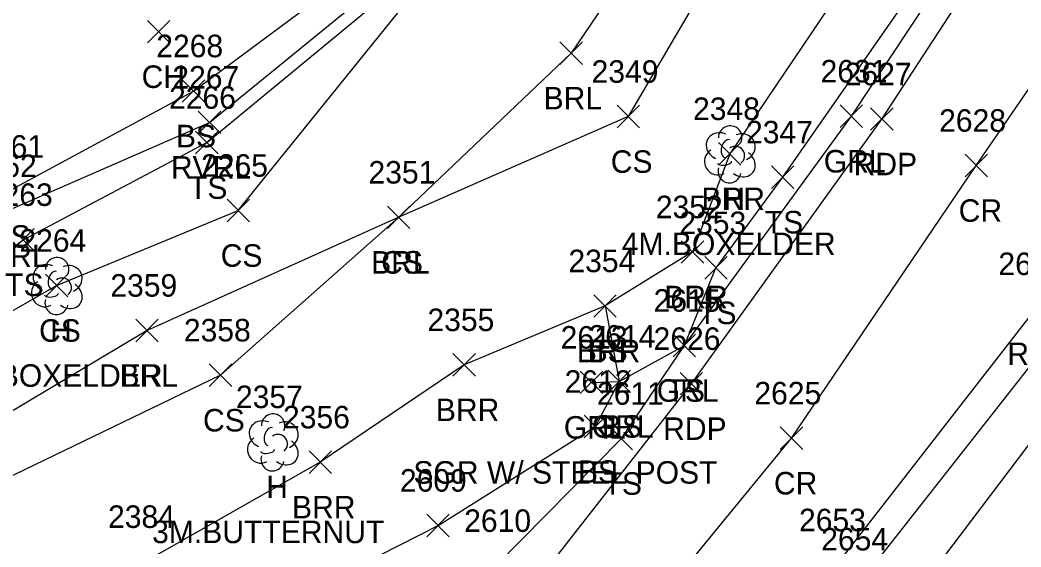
# Model space of a CAD drawing. Extents: x 1504228 to 1506103, y 437717 to 440106.
# Drawn here: x 1505331 to 1505420, y 438175.7 to 438222.5 of the extents above; entities that cross this region are included whole.
import ezdxf

# ---------------------------------------------------------------- set-up
doc = ezdxf.new("R2010")
doc.units = 0
for name, color, linetype in [('L_A', 7, 'Continuous'), ('L_C', 7, 'Continuous'), ('L_I', 7, 'Continuous'), ('L_TIC', 7, 'Continuous'), ('LABL', 7, 'Continuous'), ('LAWE', 7, 'Continuous'), ('LELB', 7, 'Continuous'), ('LTD', 7, 'Continuous'), ('P_A', 7, 'Continuous'), ('P_I', 7, 'Continuous'), ('P_TIC', 7, 'Continuous'), ('PET', 7, 'Continuous'), ('PRC', 7, 'Continuous'), ('R_A', 7, 'Continuous'), ('R_C', 7, 'Continuous'), ('R_I', 7, 'Continuous'), ('R_TIC', 7, 'Continuous'), ('RGR', 7, 'Continuous')]:
    doc.layers.add(name, color=color, linetype=linetype)

msp = doc.modelspace()

# ---------------------------------------------------------------- linework, layer by layer
at = {"layer": 'L_TIC'}
for points in [[(1505342.299, 438220.489), (1505344.299, 438222.489)], [(1505344.299, 438220.489), (1505342.299, 438222.489)], [(1505378.992, 438218.583), (1505380.992, 438220.583)], [(1505380.992, 438218.583), (1505378.992, 438220.583)], [(1505345.396, 438215.217), (1505347.396, 438217.217)], [(1505347.396, 438215.217), (1505345.396, 438217.217)], [(1505384.067, 438212.947), (1505386.067, 438214.947)], [(1505386.067, 438212.947), (1505384.067, 438214.947)], [(1505346.823, 438212.433), (1505348.823, 438214.433)], [(1505348.823, 438212.433), (1505346.823, 438214.433)], [(1505346.587, 438210.637), (1505348.587, 438212.637)], [(1505348.587, 438210.637), (1505346.587, 438212.637)], [(1505393.085, 438209.643), (1505395.085, 438211.643)], [(1505395.085, 438209.643), (1505393.085, 438211.643)], [(1505397.795, 438207.567), (1505399.795, 438209.567)], [(1505399.795, 438207.567), (1505397.795, 438209.567)], [(1505349.38, 438204.602), (1505351.38, 438206.602)], [(1505351.38, 438204.602), (1505349.38, 438206.602)], [(1505363.652, 438203.996), (1505365.652, 438205.996)], [(1505365.652, 438203.996), (1505363.652, 438205.996)], [(1505363.652, 438203.996), (1505365.652, 438205.996)], [(1505365.652, 438203.996), (1505363.652, 438205.996)], [(1505330.239, 438202.009), (1505332.239, 438204.009)], [(1505332.239, 438202.009), (1505330.239, 438204.009)], [(1505389.776, 438200.917), (1505391.776, 438202.917)], [(1505391.776, 438200.917), (1505389.776, 438202.917)], [(1505391.864, 438199.506), (1505393.864, 438201.506)], [(1505393.864, 438199.506), (1505391.864, 438201.506)], [(1505333.224, 438197.941), (1505335.224, 438199.941)], [(1505335.224, 438197.941), (1505333.224, 438199.941)], [(1505382.002, 438196.122), (1505384.002, 438198.122)], [(1505384.002, 438196.122), (1505382.002, 438198.122)], [(1505382.002, 438196.122), (1505384.002, 438198.122)], [(1505384.002, 438196.122), (1505382.002, 438198.122)], [(1505341.27, 438193.948), (1505343.27, 438195.948)], [(1505343.27, 438193.948), (1505341.27, 438195.948)], [(1505389.057, 438192.61), (1505391.057, 438194.61)], [(1505391.057, 438192.61), (1505389.057, 438194.61)], [(1505369.464, 438190.891), (1505371.464, 438192.891)], [(1505371.464, 438190.891), (1505369.464, 438192.891)], [(1505347.803, 438189.971), (1505349.803, 438191.971)], [(1505349.803, 438189.971), (1505347.803, 438191.971)], [(1505383.268, 438189.42), (1505385.268, 438191.42)], [(1505385.268, 438189.42), (1505383.268, 438191.42)], [(1505383.268, 438189.42), (1505385.268, 438191.42)], [(1505385.268, 438189.42), (1505383.268, 438191.42)], [(1505381.147, 438185.406), (1505383.147, 438187.406)], [(1505383.147, 438185.406), (1505381.147, 438187.406)], [(1505383.454, 438184.345), (1505385.454, 438186.345)], [(1505385.454, 438184.345), (1505383.454, 438186.345)], [(1505356.673, 438182.248), (1505358.673, 438184.248)], [(1505358.673, 438182.248), (1505356.673, 438184.248)], [(1505367.148, 438176.626), (1505369.148, 438178.626)], [(1505369.148, 438176.626), (1505367.148, 438178.626)]]:
    msp.add_lwpolyline(points, dxfattribs=at)
at = {"layer": 'LABL'}
for points in [[(1505412.94, 438279.434), (1505408.751, 438263.902), (1505393.358, 438239.3), (1505379.992, 438219.583), (1505364.652, 438204.996), (1505342.27, 438194.948), (1505325.182, 438184.758), (1505314.631, 438179.74), (1505312.566, 438178.307), (1505308.953, 438177.263), (1505304.583, 438176.7), (1505296.615, 438175.22), (1505299.292, 438169.398), (1505303.904, 438164.856), (1505308.252, 438160.874), (1505313.047, 438161.473), (1505317.495, 438164.603), (1505327.49, 438169.4), (1505342.058, 438174.403)], [(1505426.709, 438267.128), (1505407.768, 438230.9), (1505394.085, 438210.643), (1505390.776, 438201.917), (1505383.002, 438197.122), (1505370.464, 438191.891), (1505357.673, 438183.248), (1505342.058, 438174.403)]]:
    msp.add_lwpolyline(points, dxfattribs=at)
at = {"layer": 'LAWE'}
msp.add_lwpolyline([(1505329.815, 438205.572), (1505347.823, 438213.433), (1505370.111, 438231.602), (1505379.725, 438247.791), (1505393.16, 438272.478), (1505401.036, 438286.88)], dxfattribs=at)
at = {"layer": 'LELB'}
for points in [[(1505258.116, 438181.066), (1505268.339, 438182.172), (1505278.498, 438189.358), (1505293.602, 438192.608), (1505306.445, 438196.96), (1505314.273, 438197.344), (1505329.9, 438207.293), (1505346.396, 438216.217), (1505367.728, 438232.021), (1505378.412, 438248.378), (1505391.234, 438272.553), (1505398.951, 438287.599)], [(1505287.419, 438180.921), (1505294.194, 438184.889), (1505305.914, 438191.586), (1505317.977, 438192.973), (1505331.239, 438203.009), (1505347.587, 438211.637), (1505370.579, 438230.634), (1505379.879, 438246.354), (1505394.187, 438272.178), (1505403.001, 438285.772)], [(1505464.371, 438267.578), (1505443.482, 438229.816), (1505429.783, 438207.884), (1505423.465, 438195.212), (1505405.53, 438172.403), (1505390.919, 438151.584), (1505377.655, 438135.332), (1505367.909, 438121.411), (1505365.569, 438112.166), (1505365.649, 438106.069), (1505369.049, 438099.624), (1505384, 438089.64), (1505418.55, 438070.496), (1505425.632, 438075.745)], [(1505470.06, 438267.163), (1505453.418, 438227.384), (1505434.759, 438206.384), (1505425.646, 438191.367), (1505409.704, 438170.307), (1505396.192, 438148.093), (1505385.081, 438132.429), (1505376.016, 438117.564), (1505375.312, 438100.628), (1505390.313, 438095.558), (1505425.632, 438075.745), (1505441.164, 438097.453)], [(1505433.081, 438266.273), (1505413.735, 438229.989), (1505398.795, 438208.567), (1505392.864, 438200.506)], [(1505408.751, 438263.902), (1505398.015, 438236.03), (1505385.067, 438213.947), (1505364.652, 438204.996), (1505348.803, 438190.971), (1505327.848, 438180.889), (1505316.341, 438173.385)], [(1505306.221, 438188.545), (1505319.546, 438190.519), (1505334.224, 438198.941), (1505350.38, 438205.602), (1505370.579, 438230.634)], [(1505390.057, 438193.61), (1505392.864, 438200.506)], [(1505383.002, 438197.122), (1505384.268, 438190.42)], [(1505283.082, 438168.26), (1505293.755, 438159.929), (1505303.056, 438155.723), (1505307.447, 438154.511), (1505318.234, 438150.525), (1505336.416, 438150.851), (1505352.472, 438164.545), (1505373.298, 438174.049), (1505384.454, 438185.345), (1505390.057, 438193.61)], [(1505280.724, 438166.502), (1505281.778, 438166.802), (1505283.082, 438168.26), (1505285.843, 438169.435), (1505295.117, 438166.148), (1505307.071, 438157.841), (1505319.301, 438158.173), (1505335.681, 438162.149), (1505348.978, 438167.874), (1505368.148, 438177.626), (1505382.147, 438186.406), (1505384.268, 438190.42)]]:
    msp.add_lwpolyline(points, dxfattribs=at)
at = {"layer": 'LTD'}
for p, q in [((1505394.085, 438210.643), (1505394.085, 438210.643)), ((1505394.085, 438210.643), (1505394.085, 438210.643)), ((1505334.224, 438198.941), (1505334.224, 438198.941)), ((1505334.224, 438198.941), (1505334.224, 438198.941)), ((1505353.435, 438185.05), (1505353.435, 438185.05)), ((1505353.435, 438185.05), (1505353.435, 438185.05))]:
    msp.add_line(p, q, dxfattribs=at)
for centre in [(1505394.132, 438212.077), (1505334.271, 438200.375), (1505353.482, 438186.484)]:
    msp.add_arc(centre, 1.047, 335.52715, 180.95627, dxfattribs=at)
for centre, major_axis, ratio, start_param, end_param in [((1505393.294, 438211.309), (1.21, -0.512), 0.895232, 1.570796, 4.712389), ((1505395.127, 438211.226), (-1.141, -0.483), 0.949671, 1.570796, 4.712389), ((1505393.877, 438211.101), (-0.208, -0.792), 0.645439, 3.141593, 6.283185), ((1505394.586, 438210.476), (-0.5, 0.667), 0.989748, 3.141593, 6.283185), ((1505393.002, 438209.934), (0.584, -1.042), 0.959034, 3.141593, 6.283185), ((1505395.086, 438209.81), (-1.09, 0.792), 0.841452, 1.570796, 4.712389), ((1505393.627, 438209.893), (-0.625, -0.083), 0.423636, 0, 3.141593), ((1505394.086, 438209.143), (0.265, 1.061), 0.942809, 1.570796, 4.712389), ((1505333.432, 438199.607), (1.21, -0.512), 0.895232, 1.570796, 4.712389), ((1505335.266, 438199.524), (-1.141, -0.483), 0.949671, 1.570796, 4.712389), ((1505334.016, 438199.399), (-0.208, -0.792), 0.645439, 3.141593, 6.283185), ((1505333.141, 438198.232), (0.584, -1.042), 0.959034, 3.141593, 6.283185), ((1505334.724, 438198.774), (-0.5, 0.667), 0.989748, 3.141593, 6.283185), ((1505335.224, 438198.107), (-1.09, 0.792), 0.841452, 1.570796, 4.712389), ((1505333.766, 438198.19), (-0.625, -0.083), 0.423636, 0, 3.141593), ((1505334.224, 438197.441), (0.265, 1.061), 0.942809, 1.570796, 4.712389), ((1505352.643, 438185.717), (1.21, -0.512), 0.895232, 1.570796, 4.712389), ((1505354.477, 438185.634), (-1.141, -0.483), 0.949671, 1.570796, 4.712389), ((1505353.227, 438185.508), (-0.208, -0.792), 0.645439, 3.141593, 6.283185), ((1505353.935, 438184.883), (-0.5, 0.667), 0.989748, 3.141593, 6.283185), ((1505352.352, 438184.341), (0.584, -1.042), 0.959034, 3.141593, 6.283185), ((1505354.435, 438184.217), (-1.09, 0.792), 0.841452, 1.570796, 4.712389), ((1505353.435, 438183.55), (0.265, 1.061), 0.942809, 1.570796, 4.712389), ((1505352.977, 438184.3), (-0.625, -0.083), 0.423636, 0, 3.141593)]:
    msp.add_ellipse(centre, major_axis=major_axis, ratio=ratio, start_param=start_param, end_param=end_param, dxfattribs=at)
at = {"layer": 'P_TIC'}
for points in [[(1505406.619, 438212.727), (1505408.619, 438214.727)], [(1505408.619, 438212.727), (1505406.619, 438214.727)], [(1505415.016, 438208.597), (1505417.016, 438210.597)], [(1505417.016, 438208.597), (1505415.016, 438210.597)], [(1505389.677, 438189.218), (1505391.677, 438191.218)], [(1505391.677, 438189.218), (1505389.677, 438191.218)], [(1505398.585, 438184.376), (1505400.585, 438186.376)], [(1505400.585, 438184.376), (1505398.585, 438186.376)]]:
    msp.add_lwpolyline(points, dxfattribs=at)
at = {"layer": 'PET'}
for points in [[(1505462.284, 438267.741), (1505441.657, 438230.374), (1505428.151, 438208.99), (1505421.287, 438196.87), (1505403.557, 438174.106), (1505388.105, 438153.318), (1505374.877, 438136.75), (1505365.627, 438122.121), (1505363.383, 438112.135), (1505363.469, 438103.928), (1505366.164, 438099.366), (1505382.569, 438087.03)], [(1505311.676, 438134.175), (1505324.098, 438128.725), (1505335.82, 438133.23), (1505344.252, 438137.011), (1505351.761, 438143.58), (1505369.207, 438162.724), (1505390.677, 438190.218), (1505407.619, 438213.727), (1505418.189, 438229.936), (1505438.053, 438265.664)]]:
    msp.add_lwpolyline(points, dxfattribs=at)
at = {"layer": 'PRC'}
msp.add_lwpolyline([(1505338.301, 438109.134), (1505341.256, 438114.415), (1505356.739, 438132.535), (1505376.422, 438157.158), (1505399.585, 438185.376), (1505416.016, 438209.597), (1505428.391, 438227.62), (1505451.025, 438266.829)], dxfattribs=at)
at = {"layer": 'R_TIC'}
for points in [[(1505403.907, 438212.977), (1505405.907, 438214.977)], [(1505405.907, 438212.977), (1505403.907, 438214.977)], [(1505389.057, 438192.61), (1505391.057, 438194.61)], [(1505391.057, 438192.61), (1505389.057, 438194.61)], [(1505380.79, 438189.333), (1505382.79, 438191.333)], [(1505382.79, 438189.333), (1505380.79, 438191.333)], [(1505383.268, 438189.42), (1505385.268, 438191.42)], [(1505385.268, 438189.42), (1505383.268, 438191.42)]]:
    msp.add_lwpolyline(points, dxfattribs=at)
at = {"layer": 'RGR'}
msp.add_lwpolyline([(1505381.79, 438190.333), (1505384.268, 438190.42), (1505390.057, 438193.61), (1505404.907, 438213.977), (1505416.914, 438232.111), (1505436.312, 438265.645)], dxfattribs=at)

# ---------------------------------------------------------------- texts
at = {"layer": 'L_A'}
for s, p in [('CH', (1505341.787, 438216.489)), ('BRL', (1505377.535, 438214.583)), ('BS', (1505344.837, 438211.217)), ('RVRL', (1505344.39, 438208.433)), ('CS', (1505383.508, 438208.947)), ('TS', (1505345.996, 438206.637)), ('BRR', (1505391.574, 438205.643)), ('H', (1505393.519, 438205.643)), ('TS', (1505397.205, 438203.567)), ('BS', (1505328.341, 438202.293)), ('RVRL', (1505326.382, 438200.572)), ('CS', (1505348.821, 438200.602)), ('BRL', (1505362.195, 438199.996)), ('CS', (1505363.092, 438199.996)), ('TS', (1505329.649, 438198.009)), ('BRR', (1505388.264, 438196.917)), ('TS', (1505391.274, 438195.506)), ('CS', (1505332.665, 438193.941)), ('H', (1505333.657, 438193.941)), ('BRR', (1505380.49, 438192.122)), ('BS', (1505381.443, 438192.122)), ('BRL', (1505339.814, 438189.948)), ('TS', (1505388.466, 438188.61)), ('BRR', (1505367.952, 438186.891)), ('CS', (1505347.244, 438185.971)), ('BS', (1505382.709, 438185.42)), ('BS', (1505382.709, 438185.42)), ('BS', (1505380.588, 438181.406)), ('H', (1505352.868, 438180.05)), ('TS', (1505382.864, 438180.345)), ('BRR', (1505355.161, 438178.248))]:
    msp.add_text(s, height=2, dxfattribs=at).set_placement(p)
at = {"layer": 'L_C'}
for s, p in [('4M.BOXELDER', (1505384.487, 438201.643)), ('2M.BOXELDER', (1505324.626, 438189.941)), ('3M.BUTTERNUT', (1505342.719, 438176.05))]:
    msp.add_text(s, height=2, dxfattribs=at).set_placement(p)
at = {"layer": 'L_I'}
for s, p in [('2268', (1505343.089, 438219.217)), ('2267', (1505344.516, 438216.433)), ('2349', (1505381.8, 438216.947)), ('2266', (1505344.225, 438214.637)), ('2348', (1505390.826, 438213.643)), ('2348', (1505390.826, 438213.643)), ('2347', (1505395.536, 438211.567)), ('2261', (1505327.16, 438210.293)), ('2262', (1505326.508, 438208.572)), ('2265', (1505347.073, 438208.602)), ('2351', (1505361.959, 438207.996)), ('2351', (1505361.959, 438207.996)), ('2263', (1505327.932, 438206.009)), ('2352', (1505387.516, 438204.917)), ('2353', (1505389.604, 438203.506)), ('2264', (1505330.917, 438201.941)), ('2264', (1505330.917, 438201.941)), ('2354', (1505379.742, 438200.122)), ('2354', (1505379.742, 438200.122)), ('2359', (1505339.003, 438197.948)), ('2615', (1505387.317, 438196.61)), ('2355', (1505367.204, 438194.891)), ('2358', (1505345.543, 438193.971)), ('2614', (1505381.528, 438193.42)), ('2614', (1505381.528, 438193.42)), ('2612', (1505379.406, 438189.406)), ('2357', (1505350.175, 438188.05)), ('2611', (1505382.281, 438188.345)), ('2356', (1505354.358, 438186.248)), ('2609', (1505364.754, 438180.626)), ('2384', (1505338.798, 438177.403)), ('2384', (1505338.798, 438177.403)), ('2610', (1505370.471, 438177.049)), ('2610', (1505370.471, 438177.049)), ('2654', (1505402.223, 438175.403))]:
    msp.add_text(s, height=2, dxfattribs=at).set_placement(p)
at = {"layer": 'P_A'}
for s, p in [('RDP', (1505405.107, 438208.727)), ('CR', (1505414.449, 438204.597)), ('RDP', (1505418.776, 438191.87)), ('RDP', (1505388.165, 438185.218)), ('CR', (1505398.018, 438180.376))]:
    msp.add_text(s, height=2, dxfattribs=at).set_placement(p)
at = {"layer": 'P_I'}
for s, p in [('2627', (1505404.312, 438216.727)), ('2628', (1505412.709, 438212.597)), ('2652', (1505417.98, 438199.87)), ('2626', (1505387.315, 438193.218)), ('2625', (1505396.278, 438188.376)), ('2653', (1505400.249, 438177.106))]:
    msp.add_text(s, height=2, dxfattribs=at).set_placement(p)
at = {"layer": 'R_A'}
for p in [(1505402.45, 438208.977), (1505387.6, 438188.61), (1505379.333, 438185.333), (1505381.811, 438185.42)]:
    msp.add_text('GRL', height=2, dxfattribs=at).set_placement(p)
at = {"layer": 'R_C'}
msp.add_text('SGR W/ STEEL POST', height=2, dxfattribs=at).set_placement((1505365.955, 438181.333))
at = {"layer": 'R_I'}
for s, p in [('2631', (1505402.167, 438216.977)), ('2615', (1505387.317, 438196.61)), ('2613', (1505379.05, 438193.333)), ('2614', (1505381.528, 438193.42))]:
    msp.add_text(s, height=2, dxfattribs=at).set_placement(p)

doc.saveas('drawing.dxf')
